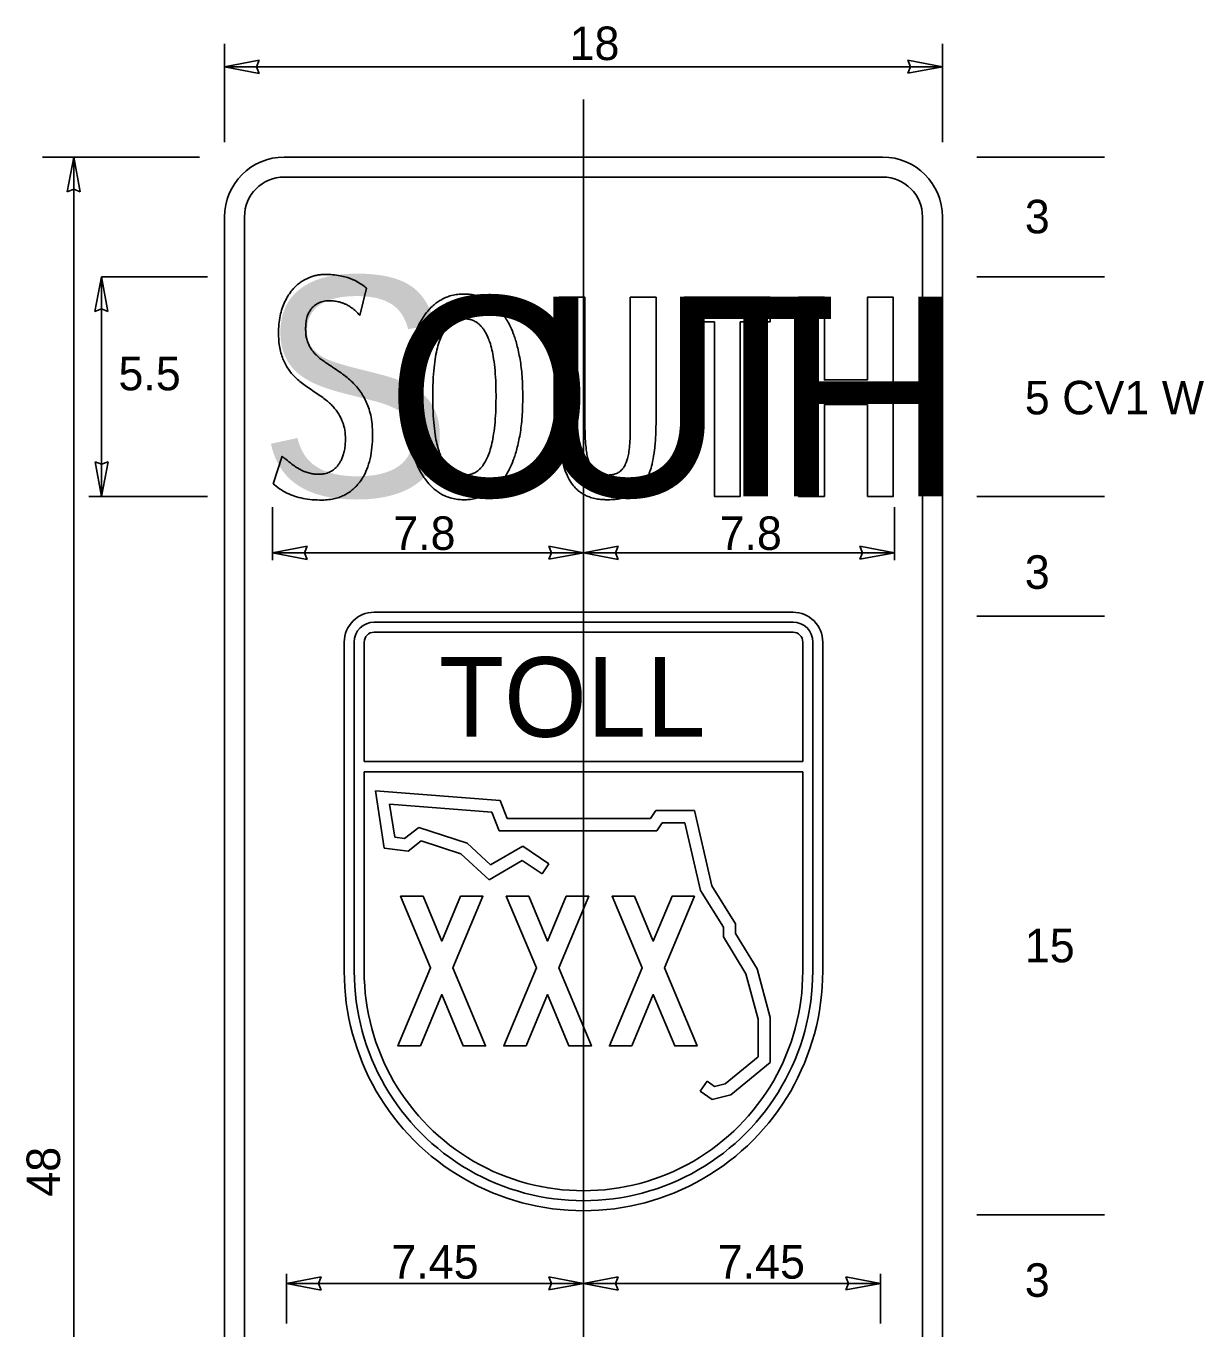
# Model space of a CAD drawing. Extents: x 56108 to 56738, y 11696 to 12112.
# Drawn here: x 56520.2 to 56618.7, y 11815.3 to 11924.1 of the extents above; entities that cross this region are included whole.
import ezdxf

# ---------------------------------------------------------------- set-up
doc = ezdxf.new("R2010")
doc.units = 0
for name, color, linetype in [('CL_dp', 7, 'Continuous'), ('GSDims', 7, 'Continuous'), ('SignDetail', 7, 'Continuous'), ('SignPanel', 7, 'Continuous')]:
    doc.layers.add(name, color=color, linetype=linetype)

msp = doc.modelspace()

# ---------------------------------------------------------------- linework, layer by layer
at = {"layer": 'CL_dp'}
msp.add_line((56566.81, 11917.97), (56566.81, 11745.62), dxfattribs=at)
at = {"layer": 'GSDims'}
for p, q in [((56536.81, 11914.4), (56536.81, 11922.62)), ((56596.81, 11914.4), (56596.81, 11922.62)), ((56539.71, 11921.24), (56536.81, 11920.7)), ((56596.81, 11920.7), (56536.81, 11920.7)), ((56536.81, 11920.7), (56539.71, 11920.14)), ((56539.49, 11920.7), (56539.71, 11921.24)), ((56539.71, 11920.14), (56539.49, 11920.7)), ((56596.81, 11920.7), (56593.91, 11921.26)), ((56593.91, 11921.26), (56594.13, 11920.7)), ((56594.13, 11920.7), (56593.91, 11920.16)), ((56593.91, 11920.16), (56596.81, 11920.7)), ((56534.73, 11913.16), (56521.6, 11913.16)), ((56524.22, 11913.16), (56523.66, 11910.26)), ((56524.22, 11913.16), (56524.22, 11753.16)), ((56524.76, 11910.26), (56524.22, 11913.16)), ((56610.35, 11913.16), (56599.67, 11913.16)), ((56523.66, 11910.26), (56524.22, 11910.48)), ((56524.22, 11910.48), (56524.76, 11910.26)), ((56526.53, 11903.16), (56525.97, 11900.26)), ((56526.53, 11903.16), (56526.53, 11884.82)), ((56527.07, 11900.26), (56526.53, 11903.16)), ((56535.4, 11903.16), (56526.53, 11903.16)), ((56610.35, 11903.16), (56599.67, 11903.16)), ((56525.97, 11900.26), (56526.53, 11900.48)), ((56526.53, 11900.48), (56527.07, 11900.26)), ((56526.53, 11887.5), (56525.99, 11887.72)), ((56525.99, 11887.72), (56526.53, 11884.82)), ((56526.53, 11884.82), (56527.09, 11887.72)), ((56527.09, 11887.72), (56526.53, 11887.5)), ((56535.4, 11884.82), (56525.48, 11884.82)), ((56610.35, 11884.82), (56599.67, 11884.82)), ((56540.81, 11883.91), (56540.81, 11879.49)), ((56592.81, 11883.91), (56592.81, 11879.49)), ((56543.71, 11880.65), (56540.81, 11880.11)), ((56543.49, 11880.11), (56543.71, 11880.65)), ((56566.81, 11880.11), (56563.91, 11880.67)), ((56563.91, 11880.67), (56564.13, 11880.11)), ((56569.71, 11880.65), (56566.81, 11880.11)), ((56569.49, 11880.11), (56569.71, 11880.65)), ((56592.81, 11880.11), (56589.91, 11880.67)), ((56589.91, 11880.67), (56590.13, 11880.11)), ((56540.81, 11880.11), (56566.81, 11880.11)), ((56540.81, 11880.11), (56543.71, 11879.55)), ((56543.71, 11879.55), (56543.49, 11880.11)), ((56564.13, 11880.11), (56563.91, 11879.57)), ((56563.91, 11879.57), (56566.81, 11880.11)), ((56566.81, 11880.11), (56592.81, 11880.11)), ((56566.81, 11880.11), (56569.71, 11879.55)), ((56569.71, 11879.55), (56569.49, 11880.11)), ((56590.13, 11880.11), (56589.91, 11879.57)), ((56589.91, 11879.57), (56592.81, 11880.11)), ((56610.35, 11874.82), (56599.67, 11874.82)), ((56554.94, 11858.73), (56554.94, 11858.73)), ((56610.35, 11824.82), (56599.67, 11824.82)), ((56541.98, 11819.88), (56541.98, 11815.75)), ((56544.88, 11819.63), (56541.98, 11819.09)), ((56544.66, 11819.09), (56544.88, 11819.63)), ((56566.81, 11819.09), (56563.91, 11819.65)), ((56563.91, 11819.65), (56564.13, 11819.09)), ((56569.71, 11819.63), (56566.81, 11819.09)), ((56569.49, 11819.09), (56569.71, 11819.63)), ((56591.64, 11819.09), (56588.74, 11819.65)), ((56588.74, 11819.65), (56588.96, 11819.09)), ((56591.64, 11819.88), (56591.64, 11815.75)), ((56541.98, 11819.09), (56566.81, 11819.09)), ((56541.98, 11819.09), (56544.88, 11818.53)), ((56544.88, 11818.53), (56544.66, 11819.09)), ((56564.13, 11819.09), (56563.91, 11818.55)), ((56563.91, 11818.55), (56566.81, 11819.09)), ((56566.81, 11819.09), (56591.64, 11819.09)), ((56566.81, 11819.09), (56569.71, 11818.53)), ((56569.71, 11818.53), (56569.49, 11819.09)), ((56588.96, 11819.09), (56588.74, 11818.55)), ((56588.74, 11818.55), (56591.64, 11819.09))]:
    msp.add_line(p, q, dxfattribs=at)
at = {"layer": 'SignDetail'}
for p, q in [((56549.31, 11875.16), (56584.32, 11875.16)), ((56549.31, 11874.32), (56584.32, 11874.32)), ((56546.81, 11845.15), (56546.81, 11872.66)), ((56547.65, 11845.15), (56547.65, 11872.66)), ((56548.47, 11862.67), (56548.47, 11872.66)), ((56549.31, 11873.48), (56584.32, 11873.48)), ((56585.14, 11862.67), (56585.14, 11872.66)), ((56585.98, 11845.15), (56585.98, 11872.66)), ((56586.81, 11845.15), (56586.81, 11872.66)), ((56548.47, 11862.67), (56585.14, 11862.67)), ((56548.47, 11845.15), (56548.47, 11861.83)), ((56548.47, 11861.83), (56585.14, 11861.83)), ((56585.14, 11845.15), (56585.14, 11861.83))]:
    msp.add_line(p, q, dxfattribs=at)
for centre, major_axis, start_param, end_param in [((56549.32, 11872.65), (0, 2.5), 0, 1.570796), ((56584.31, 11872.65), (0, 2.5), 4.712389, 6.283185), ((56549.32, 11872.65), (0, 1.67), 0, 1.570796), ((56584.31, 11872.65), (0, 1.67), 4.712389, 6.283185), ((56549.32, 11872.65), (0, 0.833), 0, 1.570796), ((56584.31, 11872.65), (0, 0.833), 4.712389, 6.283185), ((56566.81, 11845.16), (0, -20), 4.712389, 7.853982), ((56566.81, 11845.16), (0, -19.16), 4.712389, 7.853982), ((56566.81, 11845.16), (0, -18.33), 4.712389, 7.853982)]:
    msp.add_ellipse(centre, major_axis=major_axis, ratio=0.9997, start_param=start_param, end_param=end_param, dxfattribs=at)
at = {"layer": 'SignPanel'}
for p, q in [((56550.16, 11855.44), (56549.42, 11860.22)), ((56549.42, 11860.22), (56559.85, 11859.41)), ((56559.14, 11858.46), (56550.61, 11859.11)), ((56550.61, 11859.11), (56551.04, 11856.35)), ((56559.75, 11856.9), (56559.14, 11858.46)), ((56559.85, 11859.41), (56560.44, 11857.91)), ((56572.4, 11857.91), (56572.86, 11858.58)), ((56572.86, 11858.58), (56576.08, 11858.58)), ((56576.08, 11858.58), (56577.53, 11852.3)), ((56560.44, 11857.91), (56572.4, 11857.91)), ((56573.39, 11857.57), (56572.94, 11856.9)), ((56575.28, 11857.57), (56573.39, 11857.57)), ((56576.59, 11851.91), (56575.28, 11857.57)), ((56551.04, 11856.35), (56551.86, 11856.25)), ((56551.86, 11856.25), (56553.05, 11857.18)), ((56553.05, 11857.18), (56557.08, 11855.87)), ((56572.94, 11856.9), (56559.75, 11856.9)), ((56552.16, 11855.2), (56550.16, 11855.44)), ((56553.25, 11856.06), (56552.16, 11855.2)), ((56556.55, 11854.98), (56553.25, 11856.06)), ((56557.08, 11855.87), (56559.05, 11854.04)), ((56559.05, 11854.04), (56561.73, 11855.61)), ((56561.73, 11855.61), (56563.91, 11854.14)), ((56558.92, 11852.79), (56556.55, 11854.98)), ((56561.69, 11854.42), (56558.92, 11852.79)), ((56563.35, 11853.3), (56561.69, 11854.42)), ((56563.91, 11854.14), (56563.35, 11853.3)), ((56578.51, 11848.83), (56576.59, 11851.91)), ((56577.53, 11852.3), (56579.52, 11849.11)), ((56578.51, 11848.03), (56578.51, 11848.83)), ((56579.52, 11849.11), (56579.52, 11848.31)), ((56580.38, 11844.95), (56578.51, 11848.03)), ((56579.52, 11848.31), (56581.31, 11845.35)), ((56581.31, 11845.35), (56582.42, 11841.31)), ((56581.41, 11841.17), (56580.38, 11844.95)), ((56581.41, 11838.01), (56581.41, 11841.17)), ((56582.42, 11841.31), (56582.42, 11837.53)), ((56578.66, 11835.75), (56581.41, 11838.01)), ((56582.42, 11837.53), (56579.12, 11834.83)), ((56576.56, 11835.14), (56577.14, 11835.97)), ((56577.14, 11835.97), (56577.76, 11835.54)), ((56577.76, 11835.54), (56578.66, 11835.75)), ((56577.56, 11834.45), (56576.56, 11835.14)), ((56579.12, 11834.83), (56577.56, 11834.45))]:
    msp.add_line(p, q, dxfattribs=at)
for points in [[(56541.81, 11913.16), (56591.81, 11913.16)], [(56541.81, 11911.49), (56591.81, 11911.49)], [(56536.81, 11758.16), (56536.81, 11908.16)], [(56538.48, 11758.16), (56538.48, 11908.16)], [(56595.14, 11908.16), (56595.14, 11758.16)], [(56596.81, 11908.16), (56596.81, 11758.16)], [(56548.68, 11902.21), (56548.12, 11899.94)], [(56564.77, 11891.43), (56564.77, 11901.45), (56566.93, 11901.45), (56566.93, 11890.75)], [(56570.72, 11890.75), (56570.72, 11901.45), (56572.88, 11901.45), (56572.88, 11891.43)], [(56579.91, 11899.39), (56579.91, 11884.82), (56577.75, 11884.82), (56577.75, 11899.39), (56575.22, 11899.39), (56575.22, 11901.45), (56582.41, 11901.45), (56582.41, 11899.39), (56579.91, 11899.39)], [(56590.54, 11884.82), (56590.54, 11892.49), (56586.94, 11892.49), (56586.94, 11884.82), (56584.78, 11884.82), (56584.78, 11901.45), (56586.94, 11901.45), (56586.94, 11894.55), (56590.54, 11894.55), (56590.54, 11901.45), (56592.7, 11901.45), (56592.7, 11884.82), (56590.54, 11884.82)], [(56540.87, 11885.87), (56541.62, 11888.19)]]:
    msp.add_lwpolyline(points, dxfattribs=at)
for points in [[(56553.18, 11838.93), (56554.97, 11843.21), (56556.76, 11838.93), (56558.63, 11838.93), (56555.9, 11845.45), (56558.41, 11851.43), (56556.54, 11851.43), (56554.97, 11847.68), (56553.4, 11851.43), (56551.52, 11851.43), (56554.03, 11845.45), (56551.3, 11838.93)], [(56562.01, 11838.93), (56563.8, 11843.21), (56565.59, 11838.93), (56567.47, 11838.93), (56564.74, 11845.45), (56567.25, 11851.43), (56565.37, 11851.43), (56563.8, 11847.68), (56562.23, 11851.43), (56560.36, 11851.43), (56562.87, 11845.45), (56560.14, 11838.93)], [(56570.85, 11838.93), (56572.64, 11843.21), (56574.43, 11838.93), (56576.3, 11838.93), (56573.58, 11845.45), (56576.08, 11851.43), (56574.21, 11851.43), (56572.64, 11847.68), (56571.07, 11851.43), (56569.2, 11851.43), (56571.7, 11845.45), (56568.98, 11838.93)]]:
    msp.add_lwpolyline(points, close=True, dxfattribs=at)
for centre, radius, start, end in [((56541.81, 11908.16), 5, 90, 180), ((56591.81, 11908.16), 5, 0, 90), ((56541.81, 11908.16), 3.33, 90, 180), ((56591.81, 11908.16), 3.33, 0, 90)]:
    msp.add_arc(centre, radius, start, end, dxfattribs=at)
for points in [[(56541.33, 11898.49), (56541.33, 11898.67), (56541.34, 11899.21), (56541.44, 11899.9), (56541.63, 11900.54), (56541.86, 11901.11), (56542.11, 11901.57), (56542.36, 11901.92), (56542.49, 11902.08), (56542.67, 11902.28), (56542.91, 11902.51), (56543.22, 11902.75), (56543.5, 11902.91), (56543.74, 11903.03), (56543.98, 11903.13), (56544.28, 11903.24), (56544.66, 11903.32), (56544.98, 11903.35), (56545.17, 11903.36), (56545.24, 11903.36)], [(56545.24, 11903.36), (56545.4, 11903.36), (56545.87, 11903.35), (56546.48, 11903.26), (56547, 11903.13), (56547.35, 11903.01), (56547.77, 11902.83), (56548.25, 11902.55), (56548.55, 11902.31), (56548.68, 11902.21)], [(56545.5, 11901.16), (56545.43, 11901.16), (56545.27, 11901.15), (56545.04, 11901.11), (56544.83, 11901.05), (56544.65, 11900.97), (56544.49, 11900.88), (56544.34, 11900.77), (56544.22, 11900.66), (56544.13, 11900.57), (56544.04, 11900.46), (56543.94, 11900.32), (56543.78, 11900.04), (56543.65, 11899.63), (56543.6, 11899.18), (56543.59, 11898.91), (56543.59, 11898.82)], [(56548.12, 11899.94), (56548.02, 11900.05), (56547.79, 11900.29), (56547.43, 11900.59), (56547.11, 11900.79), (56546.9, 11900.89), (56546.69, 11900.97), (56546.41, 11901.06), (56546, 11901.14), (56545.69, 11901.15), (56545.5, 11901.16)], [(56551.97, 11893.15), (56551.98, 11893.75), (56552.01, 11894.89), (56552.19, 11896.28), (56552.44, 11897.54), (56552.73, 11898.45), (56553.06, 11899.18), (56553.32, 11899.64), (56553.6, 11900.06), (56553.98, 11900.51), (56554.33, 11900.84), (56554.63, 11901.07), (56554.95, 11901.27), (56555.37, 11901.48), (56555.93, 11901.64), (56556.43, 11901.71), (56556.74, 11901.71), (56556.84, 11901.71)], [(56556.84, 11901.71), (56556.95, 11901.71), (56557.25, 11901.71), (56557.75, 11901.64), (56558.31, 11901.48), (56558.74, 11901.27), (56559.05, 11901.07), (56559.35, 11900.84), (56559.71, 11900.51), (56560.09, 11900.06), (56560.36, 11899.64), (56560.62, 11899.18), (56560.95, 11898.45), (56561.25, 11897.54), (56561.52, 11896.28), (56561.71, 11894.89), (56561.73, 11893.75), (56561.74, 11893.15)], [(56543.59, 11898.82), (56543.59, 11898.72), (56543.6, 11898.43), (56543.64, 11898.1), (56543.72, 11897.84), (56543.77, 11897.69), (56543.87, 11897.43), (56544.02, 11897.16), (56544.21, 11896.91), (56544.41, 11896.68), (56544.63, 11896.47), (56544.94, 11896.22), (56545.27, 11895.99), (56545.55, 11895.81), (56545.69, 11895.72)], [(56556.84, 11899.65), (56556.78, 11899.65), (56556.61, 11899.65), (56556.35, 11899.6), (56556.12, 11899.52), (56555.92, 11899.42), (56555.76, 11899.31), (56555.61, 11899.18), (56555.44, 11899.01), (56555.25, 11898.77), (56555.01, 11898.37), (56554.81, 11897.91), (56554.59, 11897.22), (56554.44, 11896.53), (56554.32, 11895.57), (56554.23, 11894.5), (56554.22, 11893.63), (56554.21, 11893.17)], [(56559.5, 11893.17), (56559.5, 11893.64), (56559.48, 11894.52), (56559.4, 11895.6), (56559.27, 11896.56), (56559.13, 11897.25), (56558.93, 11897.87), (56558.78, 11898.21), (56558.63, 11898.51), (56558.46, 11898.78), (56558.27, 11899.02), (56558.1, 11899.19), (56557.92, 11899.33), (56557.69, 11899.48), (56557.37, 11899.6), (56557.08, 11899.65), (56556.9, 11899.65), (56556.84, 11899.65)], [(56544.19, 11893.65), (56544.01, 11893.77), (56543.65, 11894.01), (56543.22, 11894.33), (56542.8, 11894.68), (56542.49, 11895), (56542.21, 11895.35), (56541.95, 11895.74), (56541.73, 11896.18), (56541.56, 11896.66), (56541.41, 11897.22), (56541.34, 11897.83), (56541.33, 11898.31), (56541.33, 11898.49)], [(56545.69, 11895.72), (56545.89, 11895.58), (56546.3, 11895.31), (56546.81, 11894.95), (56547.32, 11894.54), (56547.69, 11894.17), (56548.03, 11893.75), (56548.36, 11893.29), (56548.64, 11892.76), (56548.83, 11892.27), (56549.05, 11891.62), (56549.16, 11890.88), (56549.18, 11890.22), (56549.18, 11890.02)], [(56546.92, 11889.6), (56546.91, 11889.74), (56546.91, 11890.11), (56546.84, 11890.53), (56546.74, 11890.87), (56546.67, 11891.08), (56546.52, 11891.41), (56546.32, 11891.77), (56546.08, 11892.09), (56545.82, 11892.4), (56545.53, 11892.68), (56545.13, 11893), (56544.7, 11893.3), (56544.36, 11893.53), (56544.19, 11893.65)], [(56556.84, 11884.54), (56556.74, 11884.54), (56556.43, 11884.55), (56555.94, 11884.62), (56555.39, 11884.78), (56554.96, 11884.98), (56554.65, 11885.19), (56554.35, 11885.42), (56553.99, 11885.74), (56553.61, 11886.2), (56553.33, 11886.62), (56553.07, 11887.08), (56552.73, 11887.82), (56552.44, 11888.73), (56552.18, 11890), (56552.01, 11891.4), (56551.98, 11892.56), (56551.97, 11893.15)], [(56554.21, 11893.17), (56554.22, 11892.7), (56554.23, 11891.8), (56554.32, 11890.71), (56554.44, 11889.74), (56554.59, 11889.04), (56554.79, 11888.42), (56554.93, 11888.07), (56555.09, 11887.76), (56555.26, 11887.49), (56555.46, 11887.24), (56555.63, 11887.08), (56555.8, 11886.93), (56556.04, 11886.78), (56556.37, 11886.66), (56556.65, 11886.61), (56556.83, 11886.6), (56556.89, 11886.6)], [(56561.74, 11893.15), (56561.73, 11892.56), (56561.71, 11891.4), (56561.52, 11890), (56561.25, 11888.74), (56560.95, 11887.82), (56560.62, 11887.09), (56560.36, 11886.62), (56560.09, 11886.2), (56559.71, 11885.74), (56559.35, 11885.42), (56559.05, 11885.19), (56558.74, 11884.98), (56558.31, 11884.78), (56557.75, 11884.62), (56557.25, 11884.55), (56556.95, 11884.54), (56556.84, 11884.54)], [(56556.89, 11886.6), (56556.95, 11886.6), (56557.12, 11886.61), (56557.32, 11886.64), (56557.51, 11886.7), (56557.64, 11886.75), (56557.81, 11886.84), (56557.97, 11886.95), (56558.12, 11887.08), (56558.29, 11887.26), (56558.48, 11887.5), (56558.72, 11887.91), (56558.92, 11888.38), (56559.13, 11889.08), (56559.27, 11889.78), (56559.4, 11890.74), (56559.48, 11891.82), (56559.5, 11892.71), (56559.5, 11893.17)], [(56568.84, 11884.54), (56568.74, 11884.54), (56568.45, 11884.55), (56568, 11884.59), (56567.49, 11884.7), (56567.11, 11884.84), (56566.83, 11884.98), (56566.57, 11885.14), (56566.28, 11885.37), (56565.96, 11885.7), (56565.74, 11886.01), (56565.58, 11886.29), (56565.31, 11886.85), (56565.09, 11887.58), (56564.9, 11888.69), (56564.8, 11889.9), (56564.78, 11890.89), (56564.77, 11891.43)], [(56572.88, 11891.43), (56572.87, 11890.89), (56572.86, 11889.9), (56572.76, 11888.69), (56572.59, 11887.66), (56572.41, 11887.01), (56572.2, 11886.51), (56572.1, 11886.29), (56571.94, 11886.01), (56571.72, 11885.7), (56571.41, 11885.37), (56571.11, 11885.14), (56570.86, 11884.98), (56570.58, 11884.84), (56570.2, 11884.7), (56569.69, 11884.59), (56569.23, 11884.55), (56568.94, 11884.54), (56568.84, 11884.54)], [(56549.18, 11890.02), (56549.18, 11889.8), (56549.17, 11889.18), (56549.05, 11888.21), (56548.79, 11887.24), (56548.48, 11886.55), (56548.22, 11886.15), (56548.04, 11885.91), (56547.84, 11885.69), (56547.58, 11885.43), (56547.25, 11885.17), (56546.88, 11884.95), (56546.49, 11884.77), (56546.07, 11884.64), (56545.55, 11884.54), (56545.17, 11884.52), (56544.93, 11884.51)], [(56566.93, 11890.75), (56566.94, 11890.41), (56566.94, 11889.79), (56567, 11889.04), (56567.08, 11888.41), (56567.17, 11887.98), (56567.29, 11887.64), (56567.39, 11887.43), (56567.49, 11887.25), (56567.63, 11887.06), (56567.77, 11886.93), (56567.89, 11886.84), (56568.02, 11886.77), (56568.2, 11886.69), (56568.44, 11886.63), (56568.65, 11886.61), (56568.79, 11886.6), (56568.84, 11886.6)], [(56568.84, 11886.6), (56568.88, 11886.6), (56569.02, 11886.61), (56569.23, 11886.63), (56569.47, 11886.69), (56569.65, 11886.77), (56569.78, 11886.84), (56569.9, 11886.93), (56570.04, 11887.06), (56570.18, 11887.25), (56570.28, 11887.43), (56570.38, 11887.64), (56570.5, 11887.98), (56570.59, 11888.41), (56570.67, 11889.04), (56570.71, 11889.79), (56570.72, 11890.41), (56570.72, 11890.75)], [(56544.74, 11886.67), (56544.77, 11886.67), (56544.88, 11886.67), (56545.05, 11886.69), (56545.28, 11886.74), (56545.48, 11886.8), (56545.67, 11886.89), (56545.82, 11886.98), (56546, 11887.11), (56546.14, 11887.24), (56546.24, 11887.35), (56546.34, 11887.48), (56546.48, 11887.69), (56546.62, 11887.96), (56546.74, 11888.27), (56546.85, 11888.68), (56546.91, 11889.13), (56546.91, 11889.48), (56546.92, 11889.6)], [(56541.62, 11888.19), (56541.85, 11887.99), (56542.2, 11887.69), (56542.69, 11887.34), (56542.99, 11887.14), (56543.31, 11886.97), (56543.64, 11886.83), (56544.06, 11886.72), (56544.43, 11886.67), (56544.66, 11886.67), (56544.74, 11886.67)], [(56544.93, 11884.51), (56544.72, 11884.52), (56544.13, 11884.53), (56543.36, 11884.63), (56542.66, 11884.83), (56542.03, 11885.09), (56541.42, 11885.43), (56541.01, 11885.76), (56540.87, 11885.87)]]:
    msp.add_open_spline(points, degree=3, dxfattribs=at)

# ---------------------------------------------------------------- texts
at = {"layer": 'GSDims'}
for s, p in [('18', (56565.65, 11921.26)), ('3', (56603.69, 11906.79)), ('5.5', (56527.95, 11893.68)), ('5 CV1 W', (56603.69, 11891.67)), ('7.8', (56550.91, 11880.35)), ('7.8', (56578.18, 11880.35)), ('3', (56603.69, 11877.1)), ('15', (56603.69, 11845.91)), ('7.45', (56550.76, 11819.49)), ('7.45', (56578.03, 11819.49)), ('3', (56603.69, 11817.97))]:
    msp.add_text(s, height=2.8, dxfattribs=at).set_placement(p)
msp.add_text('48', height=2.8, rotation=90, dxfattribs=at).set_placement((56523.07, 11826.33))
at = {"layer": 'SignDetail'}
msp.add_text('TOLL', height=6.659, dxfattribs=at).set_placement((56554.73, 11864.74))
at = {"layer": 'SignPanel'}
for s, height, p in [('S', 18.33, (56539.58, 11884.82)), ('S', 18.33, (56539.58, 11884.82)), ('O', 16.67, (56550.28, 11884.82)), ('O', 16.67, (56550.28, 11884.82)), ('U', 16.67, (56562.57, 11884.82)), ('U', 16.67, (56562.57, 11884.82)), ('T', 16.67, (56574.39, 11884.82)), ('T', 16.67, (56574.39, 11884.82)), ('H', 16.67, (56582.58, 11884.82)), ('H', 16.67, (56582.58, 11884.82))]:
    msp.add_text(s, height=height, dxfattribs=at).set_placement(p)

doc.saveas('drawing.dxf')
